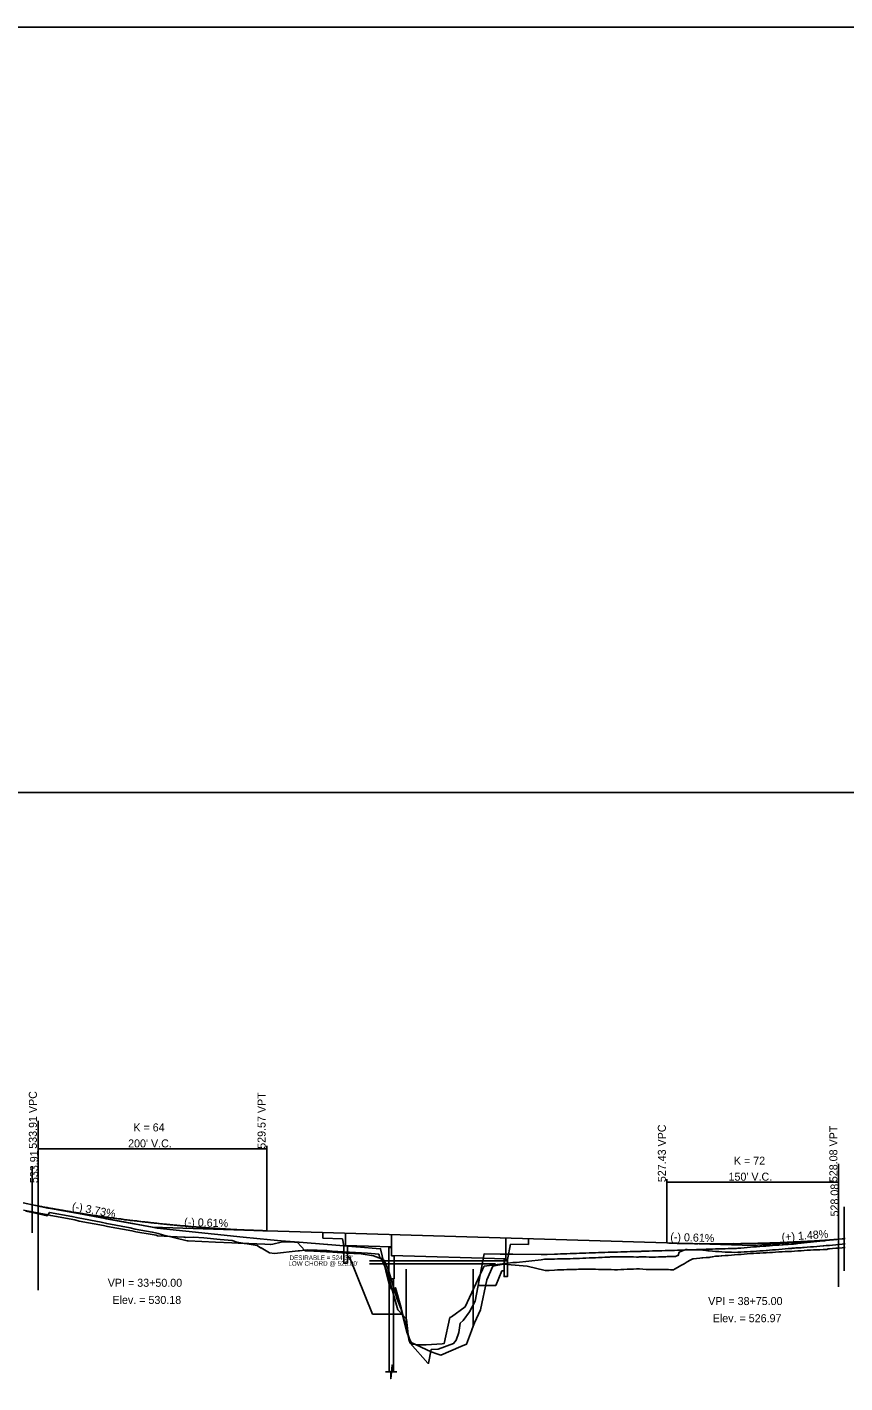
# Model space of a CAD drawing. Extents: x 1979167 to 1986508, y 1111793 to 1113993.
# Drawn here: x 1984680 to 1985395, y 1112807 to 1113993 of the extents above; entities that cross this region are included whole.
import ezdxf

# ---------------------------------------------------------------- set-up
doc = ezdxf.new("R2010")
doc.units = 0
for name, color, linetype in [('BR_CONCRETE', 7, 'Continuous'), ('BR_EXIST_GROUND_LT', 7, 'Continuous'), ('BR_EXIST_GROUND_RT', 7, 'Continuous'), ('BR_USER NOTES', 7, 'Continuous'), ('RD_DDB_GradeTX', 7, 'Continuous'), ('RD_DDB_Profile_EX', 7, 'Continuous'), ('RD_DDB_Profile_Lbl', 7, 'Continuous'), ('RD_DDB_Profile_PR', 7, 'Continuous'), ('RD_DDB_StripGrade', 7, 'Continuous'), ('RD_DDB_VCLbl', 7, 'Continuous'), ('RD_SHT_IplotShp', 7, 'Continuous'), ('RD_SHT_ShtClip', 7, 'Continuous'), ('RD_Sketch3', 7, 'Continuous')]:
    doc.layers.add(name, color=color, linetype=linetype)

msp = doc.modelspace()

# ---------------------------------------------------------------- linework, layer by layer
at = {"layer": 'BR_CONCRETE'}
for p, q in [((1984938.2, 1112933.4), (1984938.2, 1112938.4)), ((1984938.2, 1112933.4), (1984955.5, 1112932.8)), ((1984956.7, 1112926.6), (1984955.5, 1112932.8)), ((1984958.2, 1112927), (1984958.2, 1112937.8)), ((1984998.2, 1112918.3), (1984998.2, 1112936.5)), ((1985098.2, 1112915.2), (1985098.2, 1112933.5)), ((1985099.7, 1112914.8), (1985102.4, 1112928.3)), ((1985102.4, 1112928.3), (1985118.2, 1112927.9)), ((1985118.2, 1112927.9), (1985118.2, 1112932.9)), ((1984958.2, 1112927), (1984998.2, 1112925.8)), ((1984959.7, 1112916.8), (1984961.7, 1112916.8)), ((1984961.7, 1112916.8), (1984981.6, 1112867)), ((1984998.2, 1112925.4), (1984996, 1112925.4)), ((1984996, 1112897.9), (1984996, 1112925.4)), ((1984998.2, 1112925.4), (1984998.2, 1112917.9)), ((1984998.2, 1112918.3), (1985098.2, 1112915.2)), ((1984998.2, 1112917.9), (1985000.5, 1112917.9)), ((1985000.5, 1112917.9), (1985000.5, 1112897.9)), ((1985096.7, 1112904.8), (1985094.7, 1112904.8)), ((1985098.2, 1112915.2), (1985098.2, 1112914.8)), ((1985000.5, 1112897.9), (1984996, 1112897.9)), ((1984996.2, 1112816.4), (1984996.2, 1112897.9)), ((1985000.2, 1112816.4), (1985000.2, 1112897.9)), ((1985074, 1112892), (1985089.6, 1112892)), ((1984981.6, 1112867), (1985008.1, 1112867))]:
    msp.add_line(p, q, dxfattribs=at)
for points in [[(1984956.7, 1112926.6), (1984959.7, 1112926.6), (1984959.7, 1112911.6), (1984956.7, 1112911.6)], [(1985099.7, 1112914.8), (1985096.7, 1112914.8), (1985096.7, 1112899.8), (1985099.7, 1112899.8)]]:
    msp.add_lwpolyline(points, close=True, dxfattribs=at)
for points in [[(1985094.7, 1112904.8), (1985089.6, 1112892)], [(1984993.2, 1112816.4), (1984997.6, 1112816.4), (1984997.6, 1112810.4), (1984998.8, 1112822.4), (1984998.8, 1112816.4), (1985003.1, 1112816.4)]]:
    msp.add_lwpolyline(points, dxfattribs=at)
at = {"layer": 'BR_EXIST_GROUND_LT'}
msp.add_line((1985069.7, 1112856.9), (1985069.7, 1112906.3), dxfattribs=at)
msp.add_lwpolyline([(1984678.5, 1112957), (1984687, 1112955.2), (1984697.2, 1112952.9), (1984699.3, 1112956), (1984718.9, 1112952.4), (1984724.3, 1112951.1), (1984744.4, 1112947.4), (1984749.3, 1112946.2), (1984769.8, 1112942.5), (1984774.3, 1112941.4), (1984789.1, 1112938.7), (1984791.8, 1112938.2), (1984794.2, 1112937.5), (1984798.1, 1112936.4), (1984819.7, 1112931.1), (1984820.4, 1112931), (1984844.5, 1112929.9), (1984858.7, 1112929.4), (1984869.5, 1112928.9), (1984873.7, 1112928.7), (1984887.6, 1112928.3), (1984892.3, 1112927.8), (1984894.6, 1112928.3), (1984901.9, 1112930), (1984903.2, 1112930.3), (1984905.5, 1112930.3), (1984908.5, 1112930.2), (1984913.6, 1112930), (1984916.1, 1112929.7), (1984922.4, 1112922.5), (1984922.7, 1112922.4), (1984930.4, 1112922), (1984947.1, 1112921.2), (1984958.7, 1112920.4), (1984971.8, 1112919.8), (1984982.7, 1112918), (1984989.6, 1112915.4), (1984995, 1112902.5), (1984998.1, 1112891.4), (1985003.9, 1112870.6), (1985011.4, 1112862.7), (1985013, 1112848.8), (1985014.8, 1112842.4), (1985033.1, 1112833.9), (1985037.9, 1112832.2), (1985041.4, 1112831), (1985058.9, 1112838.6), (1985063.9, 1112840.6), (1985068.2, 1112852.4), (1985068.9, 1112854.2), (1985070.9, 1112859.4), (1985076.1, 1112870.6), (1985081.8, 1112897.1), (1985086.8, 1112909), (1985096, 1112910.7), (1985116.9, 1112909), (1985132.7, 1112905), (1985136.1, 1112905.2), (1985140.7, 1112905.4), (1985143.5, 1112905.6), (1985146.2, 1112905.7), (1985149, 1112905.8), (1985151.7, 1112905.9), (1985154.5, 1112906), (1985157.3, 1112906), (1985157.9, 1112906.1), (1985160, 1112906.1), (1985161.9, 1112906.2), (1985162.8, 1112906.2), (1985165.6, 1112906.2), (1985168.3, 1112906.2), (1985171.1, 1112906.2), (1985173.9, 1112906.2), (1985176.6, 1112906.2), (1985179.4, 1112906.1), (1985182.2, 1112906.1), (1985183, 1112906.1), (1985184.9, 1112906), (1985187.7, 1112906), (1985189.8, 1112905.9), (1985190.5, 1112905.9), (1985193.2, 1112905.8), (1985196, 1112905.7), (1985198.8, 1112905.9), (1985201.5, 1112906.1), (1985204.3, 1112906.2), (1985207, 1112906.3), (1985209.8, 1112906.4), (1985212.6, 1112906.5), (1985215.3, 1112906.6), (1985218.1, 1112906.4), (1985220.9, 1112906.1), (1985221.6, 1112906.1), (1985223.6, 1112906.1), (1985226.4, 1112906.1), (1985229.2, 1112906.1), (1985231.9, 1112906.1), (1985234.7, 1112906.1), (1985237.5, 1112906), (1985240.2, 1112906), (1985240.6, 1112905.9), (1985242.2, 1112905.7), (1985243, 1112905.7), (1985244.8, 1112905.6), (1985245.8, 1112906.2), (1985248.5, 1112907.8), (1985251.3, 1112909.4), (1985254.1, 1112911), (1985256.8, 1112912.6), (1985259.6, 1112914.1), (1985261.7, 1112915.3), (1985262.3, 1112915.4), (1985265.1, 1112915.6), (1985267.9, 1112915.9), (1985269.7, 1112916.1), (1985270.6, 1112916.1), (1985273.4, 1112916.4), (1985276.2, 1112916.6), (1985276.9, 1112916.7), (1985278.9, 1112917.1), (1985281.7, 1112917.6), (1985282.5, 1112917.7), (1985284.5, 1112917.8), (1985286.5, 1112917.9), (1985287.2, 1112918), (1985290, 1112918.2), (1985292.8, 1112918.4), (1985295.5, 1112918.6), (1985298.3, 1112918.8), (1985301.1, 1112919), (1985303.8, 1112919.2), (1985304.1, 1112919.2), (1985306.6, 1112919.4), (1985309.4, 1112919.7), (1985312.1, 1112919.9), (1985312.4, 1112919.9), (1985314.9, 1112920.1), (1985317.6, 1112920.2), (1985320.4, 1112920.4), (1985323.2, 1112920.5), (1985325.9, 1112920.7), (1985328.7, 1112920.8), (1985329.5, 1112920.9), (1985331.5, 1112921), (1985334.2, 1112921.2), (1985337, 1112921.4), (1985338, 1112921.5), (1985339.8, 1112921.6), (1985342.5, 1112921.7), (1985345.3, 1112921.8), (1985348.1, 1112921.9), (1985350.8, 1112922.1), (1985353.6, 1112922.2), (1985355.3, 1112922.3), (1985355.8, 1112922.3), (1985356.4, 1112922.3), (1985359.1, 1112922.6), (1985361.9, 1112922.8), (1985363.7, 1112923), (1985364.7, 1112923), (1985367.4, 1112923.1), (1985370.2, 1112923.2), (1985372.9, 1112923.3), (1985375.7, 1112923.4), (1985376.8, 1112923.4), (1985378.5, 1112923.5), (1985379, 1112923.6), (1985380.2, 1112924.1), (1985381.2, 1112924.2), (1985384, 1112924.4), (1985386.8, 1112924.6), (1985389.5, 1112924.8), (1985392.3, 1112925.1), (1985395.1, 1112925.4)], dxfattribs=at)
at = {"layer": 'BR_EXIST_GROUND_RT'}
msp.add_lwpolyline([(1984676.6, 1112957.9), (1984687, 1112955.9), (1984696.6, 1112954.1), (1984700.3, 1112953.2), (1984721.5, 1112949.4), (1984725.1, 1112948.4), (1984746.4, 1112944.6), (1984749.9, 1112943.7), (1984771.3, 1112939.9), (1984774.7, 1112939), (1984789.1, 1112936.5), (1984792.5, 1112935.9), (1984793.8, 1112935.5), (1984816.8, 1112934.3), (1984817.5, 1112934.2), (1984818.6, 1112934.1), (1984825.2, 1112934.4), (1984834.1, 1112933.6), (1984848.6, 1112932.3), (1984859.1, 1112931.5), (1984863, 1112929.8), (1984880.9, 1112927.1), (1984883.8, 1112925), (1984884.4, 1112924.9), (1984891.5, 1112920.5), (1984896.1, 1112920), (1984916.7, 1112922.4), (1984917.9, 1112922.2), (1984925.2, 1112923.3), (1984941.7, 1112922.5), (1984946.5, 1112922.1), (1984966.7, 1112920.8), (1984977.2, 1112920.2), (1984987.2, 1112919.4), (1984988.2, 1112916.5), (1984992, 1112913.9), (1984995.4, 1112906.2), (1985003.2, 1112880), (1985006.6, 1112871.8), (1985011.7, 1112851.3), (1985014.1, 1112845.3), (1985016.3, 1112840.7), (1985021.9, 1112840.1), (1985028.6, 1112840.1), (1985042.6, 1112841), (1985044.3, 1112841.2), (1985049.4, 1112863.9), (1985050.9, 1112864.7), (1985062.6, 1112873.5), (1985078, 1112906), (1985079.4, 1112908.9), (1985100.1, 1112911.6), (1985104.4, 1112912.1), (1985107.7, 1112912.1), (1985129.3, 1112914.6), (1985132.2, 1112915), (1985133.5, 1112915), (1985140.7, 1112915.1), (1985143.5, 1112915.2), (1985146.2, 1112915.2), (1985149, 1112915.3), (1985151.7, 1112915.4), (1985154.5, 1112915.4), (1985157.3, 1112915.6), (1985158, 1112915.6), (1985160, 1112915.7), (1985162.8, 1112915.7), (1985165.6, 1112915.8), (1985168.3, 1112916), (1985171.1, 1112916.1), (1985173.9, 1112916.2), (1985176.6, 1112916.3), (1985179.4, 1112916.4), (1985182.4, 1112916.6), (1985184.9, 1112916.7), (1985187.7, 1112916.9), (1985188.9, 1112916.9), (1985189.7, 1112917), (1985190.5, 1112917), (1985193.2, 1112917), (1985196, 1112917.1), (1985198.8, 1112917.1), (1985201.5, 1112917.1), (1985204.3, 1112917.2), (1985206.8, 1112917.2), (1985209.8, 1112917.1), (1985212.6, 1112916.9), (1985213.9, 1112916.9), (1985214.9, 1112917), (1985215.3, 1112917), (1985218.1, 1112917), (1985220.9, 1112917), (1985223.6, 1112916.9), (1985226.4, 1112916.9), (1985229.2, 1112916.9), (1985231.9, 1112917), (1985234.7, 1112917), (1985237.5, 1112917), (1985238.3, 1112917.1), (1985239.5, 1112917.3), (1985240.2, 1112917.3), (1985243, 1112917.4), (1985245.8, 1112917.5), (1985246.6, 1112917.5), (1985248.5, 1112918.2), (1985249, 1112918.3), (1985249.9, 1112921.1), (1985251.3, 1112921.7), (1985252.9, 1112922.3), (1985254.1, 1112922.8), (1985255.8, 1112923.4), (1985256.8, 1112923.4), (1985259.6, 1112923.3), (1985262.4, 1112923.2), (1985265.1, 1112923.2), (1985267.9, 1112923.2), (1985269.1, 1112923.2), (1985270.6, 1112923), (1985273.4, 1112922.5), (1985274.9, 1112922.3), (1985276.2, 1112922.2), (1985278.9, 1112922), (1985281.7, 1112921.8), (1985284.5, 1112921.7), (1985287.2, 1112921.5), (1985290, 1112921.3), (1985292.8, 1112921.2), (1985295.5, 1112921.1), (1985298.3, 1112920.9), (1985301.1, 1112921.1), (1985301.9, 1112921.1), (1985303.8, 1112921.2), (1985306.6, 1112921.4), (1985309.4, 1112921.5), (1985312.1, 1112921.7), (1985314.9, 1112921.9), (1985317.6, 1112922.1), (1985320.4, 1112922.3), (1985322.6, 1112922.4), (1985323.2, 1112922.4), (1985325.9, 1112922.6), (1985327.3, 1112922.7), (1985328.7, 1112922.8), (1985331.5, 1112923.1), (1985334.2, 1112923.3), (1985337, 1112923.5), (1985339.8, 1112923.8), (1985342.5, 1112924), (1985345.3, 1112924.3), (1985347, 1112924.4), (1985348.1, 1112924.5), (1985348.6, 1112924.6), (1985350.8, 1112924.8), (1985351.9, 1112924.9), (1985353.6, 1112925), (1985356.4, 1112925.1), (1985357.7, 1112925.2), (1985359.1, 1112925.3), (1985361.9, 1112925.5), (1985364.7, 1112925.7), (1985367.4, 1112925.9), (1985370.2, 1112926.2), (1985372.9, 1112926.4), (1985375.7, 1112926.7), (1985376.3, 1112926.7), (1985378.5, 1112926.9), (1985381.2, 1112927.1), (1985384, 1112927.2), (1985386.8, 1112927.5), (1985389.5, 1112927.8), (1985392.3, 1112928.1), (1985395.1, 1112928.4)], dxfattribs=at)
at = {"layer": 'BR_USER NOTES'}
for p, q in [((1984689.2, 1113036), (1984689.2, 1112887.8)), ((1984684.2, 1112995.7), (1984684.2, 1112938)), ((1985389.2, 1112998.3), (1985389.2, 1112890.9)), ((1984684.2, 1112962.6), (1984689.2, 1112961.6)), ((1985394.2, 1112960.9), (1985394.2, 1112904.8)), ((1985389.2, 1112932.4), (1985394.2, 1112932.9)), ((1984979.2, 1112913.5), (1985099.2, 1112913.5)), ((1984979.2, 1112911), (1985089.2, 1112911)), ((1985011.2, 1112854.8), (1985011.2, 1112906.3))]:
    msp.add_line(p, q, dxfattribs=at)
at = {"layer": 'RD_DDB_GradeTX'}
for p, q in [((1984710.6, 1112957.6), (1984789.2, 1112942.9)), ((1984869.2, 1112940.5), (1984789.2, 1112942.9)), ((1985239.2, 1112929.2), (1985314.2, 1112926.9)), ((1985389.2, 1112932.4), (1985314.2, 1112926.9))]:
    msp.add_line(p, q, dxfattribs=at)
at = {"layer": 'RD_DDB_Profile_EX'}
msp.add_lwpolyline([(1984676.2, 1112964.2), (1984687, 1112962), (1984697.9, 1112959.8), (1984700, 1112959.5), (1984722.9, 1112955.2), (1984724.5, 1112955), (1984747.9, 1112950.6), (1984748.9, 1112950.4), (1984772.9, 1112946), (1984773.3, 1112946), (1984789.1, 1112943), (1984793.5, 1112942.2), (1984818.5, 1112939.6), (1984843.5, 1112937), (1984868.5, 1112934.4), (1984892.6, 1112931.9), (1984901.9, 1112931.1), (1984917.5, 1112929.9), (1984942.2, 1112927.9), (1984942.5, 1112927.8), (1984967.1, 1112925.9), (1984967.6, 1112925.8), (1984988.3, 1112924.1), (1984988.7, 1112924.1), (1984990.2, 1112918), (1984996.4, 1112892.9), (1984998, 1112889), (1985001.8, 1112890), (1985006.7, 1112872.5), (1985011.2, 1112854.8), (1985013.3, 1112846.5), (1985013.6, 1112844.8), (1985014.5, 1112841.7), (1985030.2, 1112824), (1985030.8, 1112824), (1985033, 1112836.1), (1985039.1, 1112836.3), (1985052.6, 1112841.3), (1985054.9, 1112844.3), (1985057.1, 1112850.9), (1985058.4, 1112859.1), (1985061.1, 1112861.5), (1985066.5, 1112868.9), (1985071.5, 1112878.4), (1985079.2, 1112919.6), (1985093.3, 1112919.5), (1985104.4, 1112919.4), (1985129.2, 1112919.2), (1985134.4, 1112919.1), (1985140.7, 1112919.4), (1985143.5, 1112919.5), (1985146.2, 1112919.6), (1985149, 1112919.7), (1985151.7, 1112919.8), (1985154.5, 1112919.9), (1985157.3, 1112920), (1985158, 1112920), (1985159.4, 1112920.1), (1985160, 1112920.1), (1985162.8, 1112920.2), (1985165.6, 1112920.3), (1985168.3, 1112920.4), (1985171.1, 1112920.5), (1985173.9, 1112920.6), (1985176.6, 1112920.7), (1985179.4, 1112920.8), (1985182.2, 1112920.9), (1985183.5, 1112920.9), (1985184.4, 1112920.9), (1985184.9, 1112921), (1985187.7, 1112921.1), (1985190.5, 1112921.1), (1985191.2, 1112921.2), (1985191.7, 1112921.2), (1985193.2, 1112921.2), (1985196, 1112921.3), (1985198.8, 1112921.4), (1985201.5, 1112921.5), (1985204.3, 1112921.6), (1985207, 1112921.7), (1985209.8, 1112921.7), (1985212.6, 1112921.8), (1985215.3, 1112921.9), (1985216.2, 1112921.9), (1985217.1, 1112922), (1985218.1, 1112922), (1985220.9, 1112922.1), (1985223.6, 1112922.1), (1985226.4, 1112922.2), (1985229.2, 1112922.3), (1985231.9, 1112922.4), (1985234.7, 1112922.4), (1985237.5, 1112922.5), (1985240.2, 1112922.5), (1985241.2, 1112922.6), (1985242.9, 1112922.6), (1985245.8, 1112922.7), (1985248.5, 1112922.8), (1985248.5, 1112922.8), (1985251.3, 1112922.9), (1985254.1, 1112923), (1985256.8, 1112923.1), (1985259.6, 1112923.2), (1985262.3, 1112923.3), (1985265.1, 1112923.4), (1985267.9, 1112923.5), (1985270.1, 1112923.6), (1985270.6, 1112923.6), (1985273.4, 1112923.7), (1985276.2, 1112923.8), (1985278.9, 1112923.9), (1985281.7, 1112924), (1985284.5, 1112924.1), (1985287.2, 1112924.1), (1985290, 1112924.2), (1985292.8, 1112924.3), (1985295.5, 1112924.4), (1985298.3, 1112924.5), (1985300, 1112924.5), (1985300.1, 1112924.5), (1985301.1, 1112924.6), (1985303.8, 1112924.8), (1985306.6, 1112925.1), (1985309.4, 1112925.3), (1985312.1, 1112925.5), (1985314.9, 1112925.7), (1985317.6, 1112925.9), (1985320.4, 1112926.2), (1985323.2, 1112926.4), (1985325, 1112926.5), (1985325.5, 1112926.5), (1985325.9, 1112926.6), (1985328.7, 1112926.8), (1985331.5, 1112927), (1985334.2, 1112927.2), (1985337, 1112927.4), (1985339.8, 1112927.6), (1985340.9, 1112927.7), (1985342.5, 1112927.8), (1985345.3, 1112928), (1985348.1, 1112928.2), (1985349.6, 1112928.3), (1985350.1, 1112928.4), (1985350.8, 1112928.4), (1985352.2, 1112928.5), (1985353.6, 1112928.7), (1985356.4, 1112929), (1985359.1, 1112929.3), (1985361.9, 1112929.6), (1985364.7, 1112929.9), (1985367.4, 1112930.2), (1985370.2, 1112930.5), (1985372.9, 1112930.7), (1985375.7, 1112931), (1985377.2, 1112931.2), (1985378.5, 1112931.3), (1985381.2, 1112931.6), (1985384, 1112931.9), (1985386.8, 1112932.2), (1985389.5, 1112932.4), (1985392.3, 1112932.7), (1985395.1, 1112933)], dxfattribs=at)
at = {"layer": 'RD_DDB_Profile_PR'}
msp.add_line((1984889.2, 1112939.9), (1985239.2, 1112929.2), dxfattribs=at)
for points in [[(1984689.2, 1112961.6), (1984693.2, 1112960.8), (1984697.2, 1112960.1), (1984701.2, 1112959.4), (1984705.2, 1112958.7), (1984709.2, 1112958), (1984713.2, 1112957.3), (1984717.2, 1112956.6), (1984721.2, 1112956), (1984725.2, 1112955.4), (1984729.2, 1112954.7), (1984733.2, 1112954.1), (1984737.2, 1112953.5), (1984741.2, 1112952.9), (1984745.2, 1112952.3), (1984749.2, 1112951.8), (1984753.2, 1112951.2), (1984757.2, 1112950.7), (1984761.2, 1112950.2), (1984765.2, 1112949.6), (1984769.2, 1112949.1), (1984773.2, 1112948.7), (1984777.2, 1112948.2), (1984781.2, 1112947.7), (1984785.2, 1112947.3), (1984789.2, 1112946.8), (1984793.2, 1112946.4), (1984797.2, 1112946), (1984801.2, 1112945.6), (1984805.2, 1112945.2), (1984809.2, 1112944.8), (1984813.2, 1112944.4), (1984817.2, 1112944.1), (1984821.2, 1112943.7), (1984825.2, 1112943.4), (1984829.2, 1112943.1), (1984833.2, 1112942.8), (1984837.2, 1112942.5), (1984841.2, 1112942.2), (1984845.2, 1112942), (1984849.2, 1112941.7), (1984853.2, 1112941.5), (1984857.2, 1112941.2), (1984861.2, 1112941), (1984865.2, 1112940.8), (1984869.2, 1112940.6), (1984873.2, 1112940.4), (1984877.2, 1112940.3), (1984881.2, 1112940.1), (1984885.2, 1112940), (1984889.2, 1112939.9)], [(1985239.2, 1112929.2), (1985242.2, 1112929.1), (1985245.2, 1112929), (1985248.2, 1112928.9), (1985251.2, 1112928.8), (1985254.2, 1112928.8), (1985257.2, 1112928.7), (1985260.2, 1112928.7), (1985263.2, 1112928.6), (1985266.2, 1112928.6), (1985269.2, 1112928.6), (1985272.2, 1112928.5), (1985275.2, 1112928.5), (1985278.2, 1112928.5), (1985281.2, 1112928.5), (1985284.2, 1112928.5), (1985287.2, 1112928.5), (1985290.2, 1112928.5), (1985293.2, 1112928.5), (1985296.2, 1112928.6), (1985299.2, 1112928.6), (1985302.2, 1112928.6), (1985305.2, 1112928.7), (1985308.2, 1112928.7), (1985311.2, 1112928.8), (1985314.2, 1112928.8), (1985317.2, 1112928.9), (1985320.2, 1112929), (1985323.2, 1112929.1), (1985326.2, 1112929.1), (1985329.2, 1112929.2), (1985332.2, 1112929.3), (1985335.2, 1112929.4), (1985338.2, 1112929.5), (1985341.2, 1112929.7), (1985344.2, 1112929.8), (1985347.2, 1112929.9), (1985350.2, 1112930.1), (1985353.2, 1112930.2), (1985356.2, 1112930.4), (1985359.2, 1112930.5), (1985362.2, 1112930.7), (1985365.2, 1112930.8), (1985368.2, 1112931), (1985371.2, 1112931.2), (1985374.2, 1112931.4), (1985377.2, 1112931.6), (1985380.2, 1112931.8), (1985383.2, 1112932), (1985386.2, 1112932.2), (1985389.2, 1112932.4)]]:
    msp.add_spline(points, degree=3, dxfattribs=at)
at = {"layer": 'RD_DDB_VCLbl'}
for p, q in [((1984689.2, 1113014.1), (1984689.2, 1112961.6)), ((1984689.2, 1113011.6), (1984889.2, 1113011.6)), ((1984889.2, 1113014.1), (1984889.2, 1112939.9)), ((1985239.2, 1112984.9), (1985239.2, 1112929.2)), ((1985239.2, 1112982.4), (1985389.2, 1112982.4)), ((1985389.2, 1112984.9), (1985389.2, 1112932.4))]:
    msp.add_line(p, q, dxfattribs=at)
at = {"layer": 'RD_SHT_IplotShp'}
msp.add_lwpolyline([(1986508.5, 1113992.7), (1982908.5, 1113992.7), (1982908.5, 1111792.7), (1986508.5, 1111792.7)], close=True, dxfattribs=at)
at = {"layer": 'RD_SHT_ShtClip'}
msp.add_lwpolyline([(1984230.3, 1113323.3), (1986030.3, 1113323.3), (1986030.3, 1112223.3), (1984230.3, 1112223.3)], close=True, dxfattribs=at)
at = {"layer": 'RD_Sketch3'}
msp.add_line((1984958.2, 1112927), (1984958.2, 1112926.6), dxfattribs=at)

# ---------------------------------------------------------------- texts
at = {"layer": 'BR_USER NOTES'}
for s, p in [('533.91', (1984689.2, 1112981.6)), ('528.08', (1985389.2, 1112952.4))]:
    msp.add_text(s, height=7, rotation=90, dxfattribs=at).set_placement(p)
for s, p in [("DESIRABLE = 524.30'", (1984909.1, 1112914.3)), ("LOW CHORD @ 523.80'", (1984908.1, 1112909.3))]:
    msp.add_text(s, height=4, dxfattribs=at).set_placement(p)
at = {"layer": 'RD_DDB_GradeTX'}
for s, rotation, p in [('(-) 3.73%', 349.4357, (1984718.5, 1112958.1)), ('(-) 0.61%', 358.2495, (1984816.9, 1112944.1)), ('(+) 1.48%', 4.2265, (1985339.7, 1112930.8)), ('(-) 0.61%', 358.2495, (1985242, 1112931.1))]:
    msp.add_text(s, height=7, rotation=rotation, dxfattribs=at).set_placement(p)
at = {"layer": 'RD_DDB_Profile_Lbl'}
for s, p in [('VPI = 33+50.00', (1984750.2, 1112890.9)), ('Elev. = 530.18', (1984754.3, 1112875.9)), ('VPI = 38+75.00', (1985275.2, 1112874.9)), ('Elev. = 526.97', (1985279.2, 1112859.9))]:
    msp.add_text(s, height=7, dxfattribs=at).set_placement(p)
at = {"layer": 'RD_DDB_StripGrade'}
for s, p in [('533.91 VPC', (1984688.2, 1113011.6)), ('529.57 VPT', (1984888.2, 1113011.6)), ('527.43 VPC', (1985238.2, 1112982.4)), ('528.08 VPT', (1985388.2, 1112982.4))]:
    msp.add_text(s, height=7, rotation=90, dxfattribs=at).set_placement(p)
at = {"layer": 'RD_DDB_VCLbl'}
for s, p in [('K = 64', (1984772.6, 1113026.8)), ("200' V.C.", (1984768, 1113012.8)), ('K = 72', (1985297.7, 1112997.7)), ("150' V.C.", (1985293, 1112983.7))]:
    msp.add_text(s, height=7, dxfattribs=at).set_placement(p)

doc.saveas('drawing.dxf')
